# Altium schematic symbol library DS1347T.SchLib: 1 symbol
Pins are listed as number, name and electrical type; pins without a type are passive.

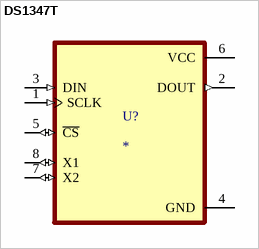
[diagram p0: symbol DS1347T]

## DS1347T
designator U?
Timer IC t- real time clock Maxim Integrated DS1347T+T&R Clock/calendar TDFN 8 EP; MP: DS1347T+T&amp;R
footprint SON65P300X300X80-9N
pins: 1 SCLK (in), 2 DOUT (out), 3 DIN (in), 4 GND (power), 5 ~{CS} (io), 6 VCC (power), 7 X2 (io), 8 X1 (io)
